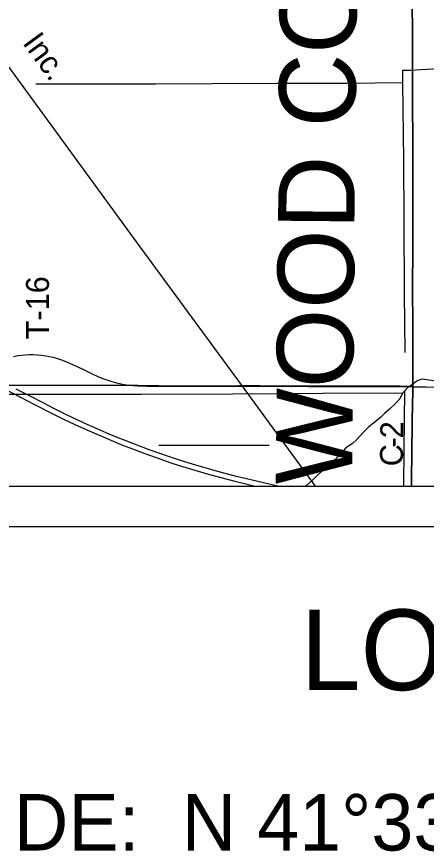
# Model space of a CAD drawing. Extents: x 0 to 34, y 0 to 22.
# Drawn here: x 3.723 to 4.739, y 13.194 to 15.265 of the extents above; entities that cross this region are included whole.
import ezdxf

# ---------------------------------------------------------------- set-up
doc = ezdxf.new("R2010")
doc.units = 0
for name, color, linetype in [('GM_X_County_Road', 7, 'Continuous'), ('GM_X_County_Road_Text', 7, 'Continuous'), ('GM_X_County_Text', 7, 'Continuous'), ('GM_X_Interstate_Location', 7, 'Continuous'), ('GM_X_Interstate_Route', 7, 'Continuous'), ('GM_X_Interstate_Shield', 7, 'Continuous'), ('GM_X_Minor_River', 7, 'Continuous'), ('GM_X_Rail_Line', 7, 'Continuous'), ('GM_X_Rail_Line_Text', 7, 'Continuous'), ('GM_X_State_Route', 7, 'Continuous'), ('GM_X_Township_Road_Text', 7, 'Continuous'), ('SH_Data', 7, 'Continuous'), ('SH_Text', 7, 'Continuous')]:
    doc.layers.add(name, color=color, linetype=linetype)

msp = doc.modelspace()

# ---------------------------------------------------------------- linework, layer by layer
at = {"layer": 'GM_X_County_Road'}
for points in [[(4.7052, 14.3464), (4.7054, 14.3911), (4.7054, 14.4409), (4.7054, 14.4719), (4.7052, 14.4954), (4.7049, 14.5933), (4.7052, 14.6897), (4.7058, 14.7393), (4.7056, 14.8947), (4.7054, 14.9662), (4.705, 15.0377), (4.7049, 15.0843), (4.7046, 15.162), (4.7042, 15.2366), (4.7035, 15.2867), (4.7038, 15.3361), (4.7038, 15.3493)], [(4.7023, 14.1), (4.7023, 14.1051), (4.7024, 14.127), (4.703, 14.1738), (4.704, 14.2638), (4.7051, 14.3352), (4.7052, 14.3464)]]:
    msp.add_lwpolyline(points, dxfattribs=at)
at = {"layer": 'GM_X_Interstate_Route'}
for points in [[(4.7033, 15.2872), (4.704, 15.2372), (4.7044, 15.1626), (4.7047, 15.0849), (4.7047, 15.0383), (4.7052, 14.9668), (4.7054, 14.8953), (4.7055, 14.7399), (4.705, 14.6903), (4.7046, 14.5938), (4.705, 14.4959), (4.7052, 14.4725), (4.7052, 14.4414), (4.7052, 14.3917), (4.705, 14.347), (4.7049, 14.3358), (4.7038, 14.2643), (4.7028, 14.1744), (4.7022, 14.1275), (4.7021, 14.1056), (4.7021, 14.1), (8.9, 14.1), (8.9, 17.3895)], [(3.7044, 14.3506), (4.0237, 14.3492), (4.0455, 14.3486), (4.0747, 14.3483), (4.0983, 14.3481), (4.1195, 14.3481), (4.1897, 14.3481), (4.227, 14.3482), (4.2606, 14.3482), (4.2737, 14.3483), (4.283, 14.3484), (4.2967, 14.3485), (4.3259, 14.3483), (4.3663, 14.3481), (4.4459, 14.3479), (4.4882, 14.3476), (4.5298, 14.3477), (4.6013, 14.3478), (4.6349, 14.3478), (4.6722, 14.3477), (4.6879, 14.3474), (4.705, 14.347), (4.7052, 14.3917), (4.7052, 14.4414), (4.7052, 14.4725), (4.705, 14.4959), (4.7046, 14.5938), (4.705, 14.6903), (4.7055, 14.7399), (4.7054, 14.8953), (4.7052, 14.9668), (4.7047, 15.0383), (4.7047, 15.0849), (4.7044, 15.1626), (4.704, 15.2372), (4.7033, 15.2872)], [(3.6138, 14.3818), (3.6731, 14.3512), (3.7118, 14.3312), (3.7687, 14.3019), (3.8141, 14.2788), (3.8392, 14.2663), (3.8655, 14.2537), (3.8898, 14.2426), (3.9216, 14.2285), (3.9565, 14.2137), (3.9858, 14.2016), (4.0124, 14.1912), (4.0409, 14.1806), (4.0801, 14.1666), (4.1077, 14.1571), (4.1343, 14.1485), (4.1646, 14.1393), (4.1956, 14.1303), (4.2292, 14.1211), (4.264, 14.1121), (4.2948, 14.1046), (4.3145, 14.1)], [(2.1, 14.1), (4.7021, 14.1), (4.7021, 14.1056), (4.7022, 14.1275), (4.7028, 14.1744), (4.7038, 14.2643), (4.7049, 14.3358), (4.705, 14.347), (4.6879, 14.3474), (4.6722, 14.3477), (4.6349, 14.3478), (4.6013, 14.3478), (4.5298, 14.3477), (4.4882, 14.3476), (4.4459, 14.3479), (4.3663, 14.3481), (4.3259, 14.3483), (4.2967, 14.3485), (4.283, 14.3484), (4.2737, 14.3483), (4.2606, 14.3482), (4.227, 14.3482), (4.1897, 14.3481), (4.1195, 14.3481), (4.0983, 14.3481), (4.0747, 14.3483), (4.0455, 14.3486), (4.0237, 14.3492), (3.7044, 14.3506)], [(3.7212, 14.3415), (3.7505, 14.3263), (3.7892, 14.3064), (3.8141, 14.2937), (3.8459, 14.2779), (3.8705, 14.266), (3.8971, 14.2537), (3.9215, 14.2428), (3.9518, 14.2298), (3.9737, 14.2208), (3.991, 14.2138), (4.0212, 14.2021), (4.0532, 14.1901), (4.0749, 14.1823), (4.1008, 14.1734), (4.131, 14.1637), (4.1667, 14.1527), (4.206, 14.1412), (4.236, 14.1329), (4.2637, 14.1257), (4.2928, 14.1187), (4.36, 14.1031), (4.3735, 14.1)]]:
    msp.add_lwpolyline(points, dxfattribs=at)
at = {"layer": 'GM_X_Interstate_Shield'}
msp.add_line((4.0757, 14.2018), (4.349, 14.2018), dxfattribs=at)
at = {"layer": 'GM_X_Minor_River'}
for points in [[(6.7224, 15.3608), (5.1099, 15.3744), (5.1125, 15.1557), (4.6992, 15.1313)], [(4.6992, 15.1313), (4.6799, 15.1309), (4.6798, 15.1005), (4.6821, 14.9085), (4.6828, 14.7609), (4.6836, 14.5776), (4.6851, 14.4312)], [(4.6794, 15.1006), (4.5428, 15.099), (4.3681, 15.0991), (4.2084, 15.0983), (4.068, 15.0975), (3.8868, 15.0974), (3.7703, 15.0974)], [(6.7502, 14.5934), (6.577, 14.5935), (6.3567, 14.5887), (6.3366, 14.5853), (6.2324, 14.4947), (6.0989, 14.3527), (5.5777, 14.3546), (4.8184, 14.3627), (4.7828, 14.3566), (4.7301, 14.365), (4.7259, 14.3643), (4.7202, 14.3628), (4.7168, 14.3609), (4.7142, 14.3594)], [(4.7142, 14.3594), (4.7105, 14.3569), (4.7065, 14.3539), (4.7016, 14.3507), (4.6943, 14.3461)], [(4.6797, 14.3307), (4.4822, 14.3293), (4.2586, 14.3284), (4.0313, 14.3272), (3.8387, 14.3269), (3.617, 14.3274), (3.3337, 14.3274), (3.12, 14.3282), (3.0054, 14.329)], [(4.6943, 14.3461), (4.6797, 14.3307), (4.6727, 14.3164), (4.6611, 14.3037), (4.6469, 14.291), (4.635, 14.2798), (4.6254, 14.2713), (4.612, 14.259), (4.5959, 14.2471), (4.581, 14.2325), (4.5671, 14.2168), (4.5548, 14.2049), (4.5391, 14.1945), (4.5287, 14.1821), (4.5156, 14.1695), (4.5037, 14.1567), (4.4884, 14.1433), (4.4773, 14.1344), (4.4673, 14.1255), (4.4554, 14.1139), (4.4419, 14.1016), (4.438, 14.1)], [(4.6843, 14.3356), (4.6828, 14.1922), (4.6819, 14.1)]]:
    msp.add_lwpolyline(points, dxfattribs=at)
at = {"layer": 'GM_X_Rail_Line'}
msp.add_lwpolyline([(4.4636, 14.1), (4.2829, 14.3475), (4.0202, 14.7061), (3.9178, 14.8467), (3.7641, 15.0572), (3.5439, 15.3588), (3.2112, 15.8143), (3.0989, 15.9678), (2.9869, 16.1219), (2.8009, 16.3767), (2.7485, 16.4478), (2.7239, 16.4783), (2.6984, 16.5122), (2.4472, 16.8567), (2.3237, 17.0297), (2.1, 17.3362)], dxfattribs=at)
at = {"layer": 'GM_X_State_Route'}
for points in [[(3.7151, 14.4214), (3.7266, 14.4237), (3.7358, 14.4251), (3.7444, 14.426), (3.7537, 14.4264), (3.7636, 14.4264), (3.7741, 14.4259), (3.7846, 14.4249), (3.795, 14.4234), (3.8041, 14.4217), (3.8132, 14.4196), (3.8239, 14.4165), (3.8345, 14.413), (3.8449, 14.4091), (3.8558, 14.4045), (3.8839, 14.3914), (3.9086, 14.3795), (3.9261, 14.3714), (3.9364, 14.3669), (3.9463, 14.3632), (3.9564, 14.3599), (3.9672, 14.3569), (3.9781, 14.3543), (3.9892, 14.3522), (4.0009, 14.3505), (4.0115, 14.3494), (4.0239, 14.3487), (4.0457, 14.348), (4.0749, 14.3477), (4.0986, 14.3476), (4.1034, 14.3476)], [(4.1034, 14.3476), (4.1197, 14.3476), (4.19, 14.3476), (4.2273, 14.3476), (4.2608, 14.3476), (4.2739, 14.3477), (4.2832, 14.3478), (4.2969, 14.3479), (4.3261, 14.3477), (4.3665, 14.3475), (4.4461, 14.3473), (4.4884, 14.3471), (4.53, 14.3471), (4.6015, 14.3473), (4.6351, 14.3472), (4.6724, 14.3471), (4.6881, 14.3469), (4.7052, 14.3464)], [(4.7052, 14.3464), (4.7134, 14.3463), (4.7383, 14.3461), (4.7569, 14.3457)]]:
    msp.add_lwpolyline(points, dxfattribs=at)
at = {"layer": 'SH_Data'}
for p, q in [((2.1, 14.1), (8.9, 14.1)), ((2, 14), (9, 14))]:
    msp.add_line(p, q, dxfattribs=at)

# ---------------------------------------------------------------- texts
at = {"layer": 'GM_X_County_Road_Text'}
for s, rotation, p in [('2', 89.4141, (4.6811, 14.2183)), ('-', 89.3784, (4.6808, 14.1951)), ('C', 89.3768, (4.6803, 14.1488))]:
    msp.add_text(s, height=0.0568, rotation=rotation, dxfattribs=at).set_placement(p)
at = {"layer": 'GM_X_County_Text'}
msp.add_text('WOOD COUNTY', height=0.189394, rotation=89.499, dxfattribs=at).set_placement((4.5547, 14.1029))
at = {"layer": 'GM_X_Interstate_Location'}
for s in ['-', '.', ',']:
    msp.add_text(s, height=0.000189, dxfattribs=at).set_placement((4.2123, 14.1263))
at = {"layer": 'GM_X_Rail_Line_Text'}
msp.add_text('Inc.', height=0.05663, rotation=306.1279, dxfattribs=at).set_placement((3.7359, 15.1992))
at = {"layer": 'GM_X_Township_Road_Text'}
msp.add_text('T-16', height=0.05682, rotation=90, dxfattribs=at).set_placement((3.8031, 14.4643))
at = {"layer": 'SH_Text'}
for s, height, p in [('LOCATION MAP', 0.2, (4.4269, 13.5938)), ('LATITUDE:  N 41°33\'31"     LONGITUDE:  W 83°24\'01"', 0.14, (3.071, 13.1959))]:
    msp.add_text(s, height=height, dxfattribs=at).set_placement(p)

doc.saveas('drawing.dxf')
